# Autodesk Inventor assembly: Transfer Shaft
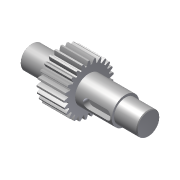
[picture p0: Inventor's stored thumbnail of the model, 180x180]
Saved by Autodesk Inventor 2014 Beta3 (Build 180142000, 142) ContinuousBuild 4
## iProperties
Created: 2011-01
Part Number: Transfer Shaft
Document SubType Name: Assembly
Designer: Beta-8540w
ClientObjectVersion: 1
Author: Beta-8540w
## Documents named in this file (2)
- C:\Inventor 2014 Essentials\Assemblies\Chapter 09\Design Accelerators\Shaft c09-03.iam
- C:\Inventor 2014 Essentials\Assemblies\Chapter 09\Design Accelerators\Shaft c09-03.ipt
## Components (1 placed, 1 different names)
1. Transfer Shaft:1
